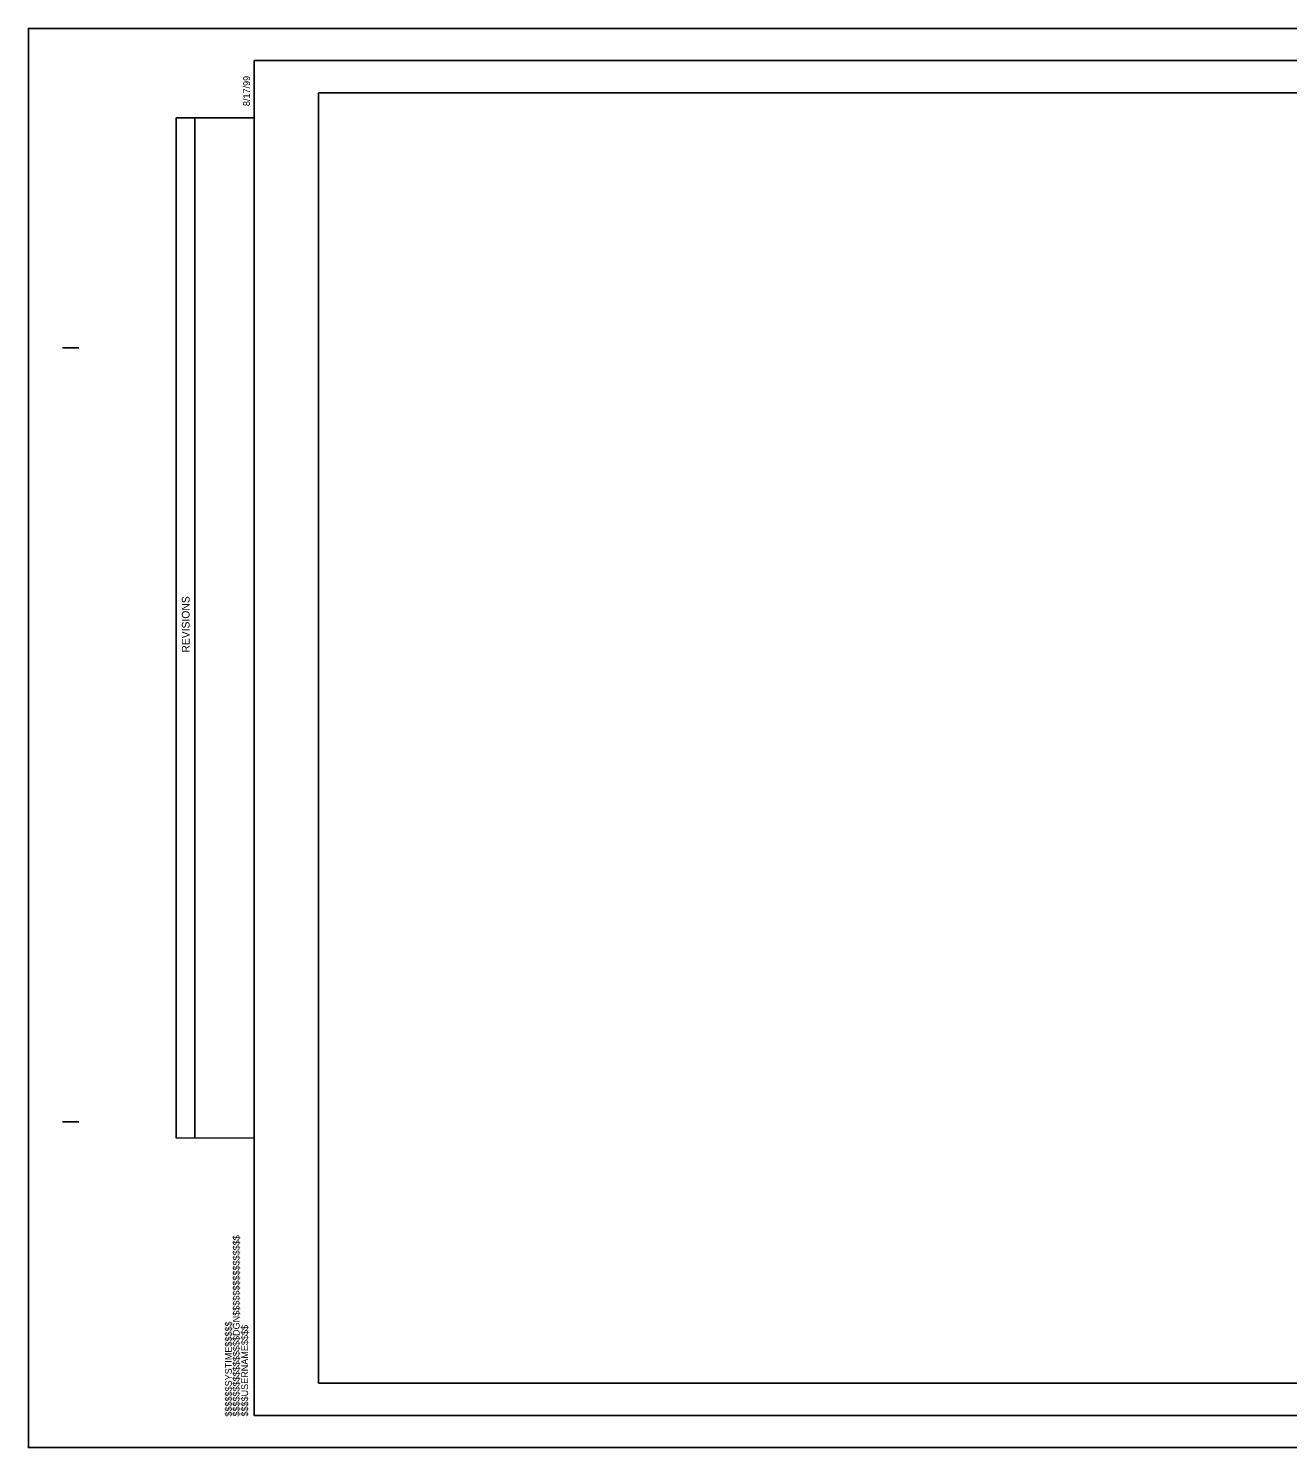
# Model space of a CAD drawing. Extents: x 573078 to 573117.1, y -55221.3 to -55199.3.
# Drawn here: x 573078.01 to 573097.54, y -55221.3 to -55199.3 of the extents above; entities that cross this region are included whole.
import ezdxf

# ---------------------------------------------------------------- set-up
doc = ezdxf.new("R2010")
doc.units = 0
for name, color, linetype in [('Sheet Block Revision CELL', 7, 'Continuous'), ('Sheet Clip Boundary CELL', 7, 'Continuous'), ('Sheet Plan CELL', 7, 'Continuous'), ('Sheet Plot Border Inside CELL', 7, 'Continuous')]:
    doc.layers.add(name, color=color, linetype=linetype)

msp = doc.modelspace()

# ---------------------------------------------------------------- linework, layer by layer
at = {"layer": 'Sheet Block Revision CELL'}
msp.add_line((573080.595, -55216.498), (573080.594, -55200.686), dxfattribs=at)
msp.add_lwpolyline([(573080.304, -55216.499), (573080.304, -55200.686), (573081.514, -55200.685), (573081.514, -55216.498)], close=True, dxfattribs=at)
at = {"layer": 'Sheet Clip Boundary CELL'}
msp.add_lwpolyline([(573082.514, -55200.298), (573107.013, -55200.298), (573107.013, -55205.473), (573110.514, -55205.473), (573110.514, -55220.298), (573082.514, -55220.298)], close=True, dxfattribs=at)
at = {"layer": 'Sheet Plan CELL'}
for p, q in [((573081.514, -55199.798), (573081.514, -55199.798)), ((573078.544, -55204.249), (573078.794, -55204.248)), ((573078.545, -55216.249), (573078.795, -55216.249)), ((573081.443, -55220.864), (573081.443, -55220.864))]:
    msp.add_line(p, q, dxfattribs=at)
msp.add_lwpolyline([(573081.514, -55199.798), (573111.514, -55199.798), (573111.514, -55220.798), (573081.514, -55220.798)], close=True, dxfattribs=at)
at = {"layer": 'Sheet Plot Border Inside CELL'}
msp.add_lwpolyline([(573112.014, -55199.298), (573078.014, -55199.298), (573078.014, -55221.298), (573112.014, -55221.298)], close=True, dxfattribs=at)

# ---------------------------------------------------------------- texts
at = {"layer": 'Sheet Block Revision CELL'}
msp.add_text('REVISIONS', height=0.12, rotation=90, dxfattribs=at).set_placement((573080.514, -55208.975))
at = {"layer": 'Sheet Plan CELL'}
for s, p in [('8/17/99', (573081.45, -55200.503)), ('$$$$$$$$$$$$$$$$DGN$$$$$$$$$$$$$$$$', (573081.29, -55220.817)), ('$$$$$$SYSTIME$$$$$', (573081.169, -55220.818)), ('$$$$USERNAME$$$$', (573081.421, -55220.817))]:
    msp.add_text(s, height=0.105, rotation=90, dxfattribs=at).set_placement(p)

doc.saveas('drawing.dxf')
